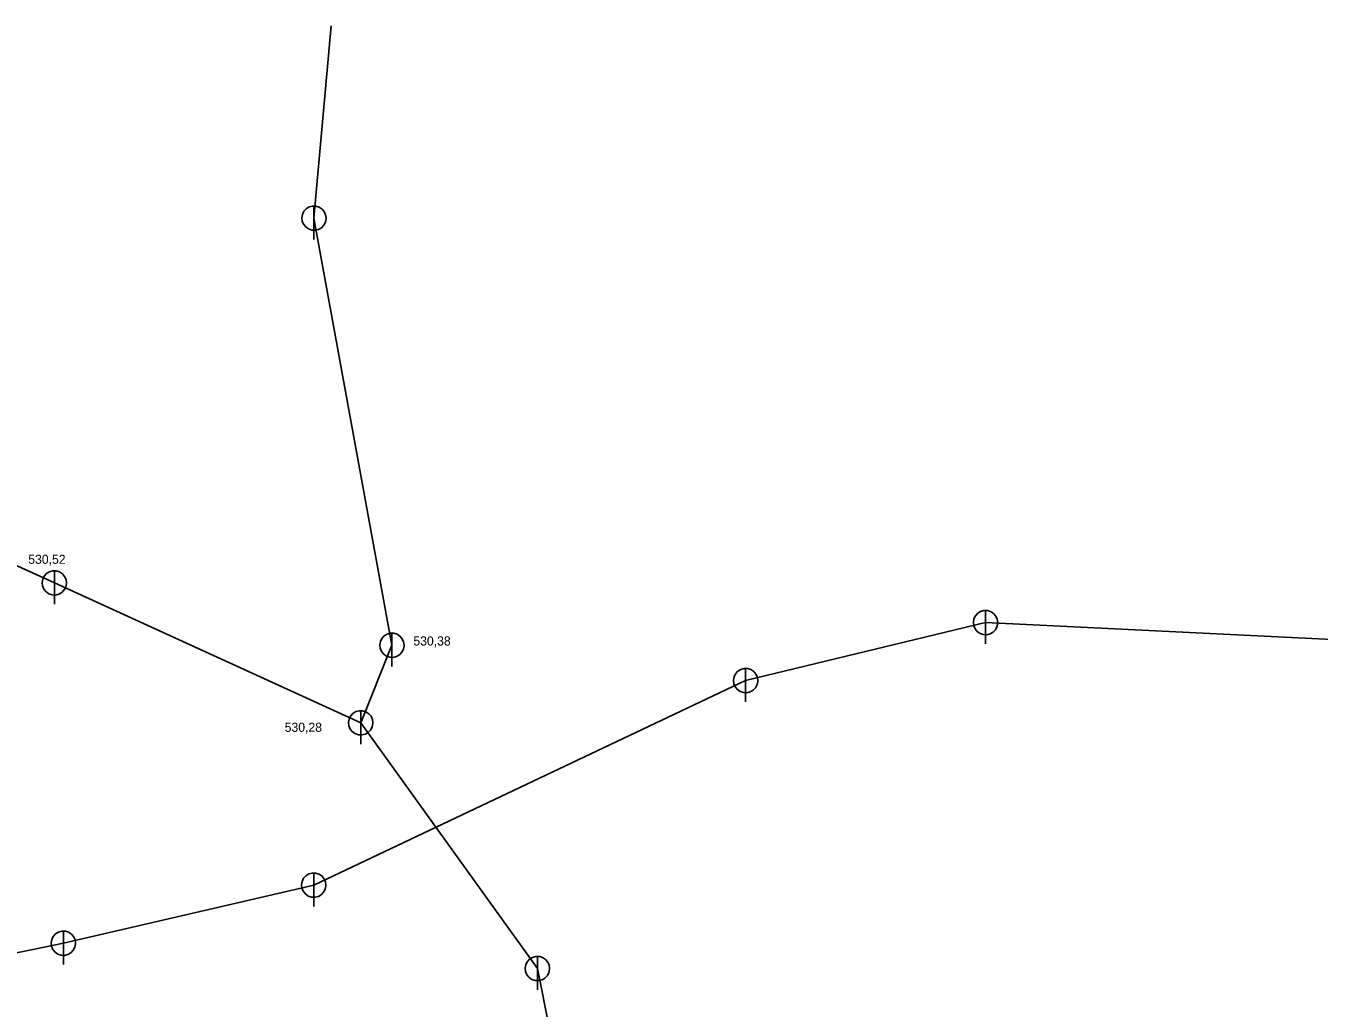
# Model space of a CAD drawing. Extents: x -476058 to -471893, y -1155786 to -1152000.
# Drawn here: x -473406.3 to -473300, y -1153831.2 to -1153750.3 of the extents above; entities that cross this region are included whole.
import ezdxf

# ---------------------------------------------------------------- set-up
doc = ezdxf.new("R2010")
doc.units = 0
for name, color, linetype in [('Vrstva 10', 7, 'Continuous'), ('Vrstva 3', 7, 'Continuous'), ('Vrstva 45', 7, 'Continuous'), ('Vrstva 46', 7, 'Continuous')]:
    doc.layers.add(name, color=color, linetype=linetype)

msp = doc.modelspace()

# ---------------------------------------------------------------- linework, layer by layer
at = {"layer": 'Vrstva 10'}
for p, q in [((-473382.66, -1153765.16), (-473382.66, -1153767.91)), ((-473404, -1153795.17), (-473404, -1153797.92)), ((-473327.45, -1153798.44), (-473327.45, -1153801.19)), ((-473376.25, -1153800.3), (-473376.25, -1153803.05)), ((-473347.17, -1153803.21), (-473347.17, -1153805.96)), ((-473378.82, -1153806.68), (-473378.82, -1153809.43)), ((-473382.68, -1153820.03), (-473382.68, -1153822.78)), ((-473403.26, -1153824.81), (-473403.26, -1153827.56)), ((-473364.29, -1153826.9), (-473364.29, -1153829.64))]:
    msp.add_line(p, q, dxfattribs=at)
for points in [[(-473381.66, -1153766.16), (-473381.7, -1153765.88), (-473381.82, -1153765.62), (-473382, -1153765.41), (-473382.23, -1153765.26), (-473382.51, -1153765.17), (-473382.79, -1153765.17), (-473383.06, -1153765.24), (-473383.3, -1153765.39), (-473383.49, -1153765.6), (-473383.61, -1153765.85), (-473383.66, -1153766.13), (-473383.63, -1153766.41), (-473383.52, -1153766.67), (-473383.34, -1153766.89), (-473383.11, -1153767.05), (-473382.84, -1153767.14), (-473382.56, -1153767.16), (-473382.29, -1153767.09), (-473382.04, -1153766.95), (-473381.85, -1153766.74), (-473381.72, -1153766.49), (-473381.66, -1153766.22), (-473381.66, -1153766.16)], [(-473403, -1153796.17), (-473403.04, -1153795.89), (-473403.16, -1153795.63), (-473403.34, -1153795.42), (-473403.58, -1153795.27), (-473403.85, -1153795.18), (-473404.13, -1153795.18), (-473404.4, -1153795.25), (-473404.64, -1153795.4), (-473404.83, -1153795.61), (-473404.96, -1153795.86), (-473405, -1153796.14), (-473404.97, -1153796.42), (-473404.86, -1153796.68), (-473404.68, -1153796.9), (-473404.45, -1153797.06), (-473404.19, -1153797.15), (-473403.9, -1153797.17), (-473403.63, -1153797.1), (-473403.39, -1153796.96), (-473403.19, -1153796.75), (-473403.06, -1153796.5), (-473403.01, -1153796.23), (-473403, -1153796.17)], [(-473326.45, -1153799.44), (-473326.49, -1153799.16), (-473326.61, -1153798.9), (-473326.79, -1153798.69), (-473327.03, -1153798.53), (-473327.29, -1153798.45), (-473327.58, -1153798.45), (-473327.85, -1153798.52), (-473328.09, -1153798.67), (-473328.28, -1153798.88), (-473328.4, -1153799.13), (-473328.45, -1153799.41), (-473328.42, -1153799.69), (-473328.31, -1153799.95), (-473328.13, -1153800.17), (-473327.9, -1153800.33), (-473327.63, -1153800.42), (-473327.35, -1153800.44), (-473327.08, -1153800.37), (-473326.83, -1153800.23), (-473326.64, -1153800.02), (-473326.51, -1153799.77), (-473326.45, -1153799.5), (-473326.45, -1153799.44)], [(-473375.25, -1153801.3), (-473375.29, -1153801.02), (-473375.41, -1153800.76), (-473375.59, -1153800.55), (-473375.83, -1153800.4), (-473376.1, -1153800.31), (-473376.38, -1153800.31), (-473376.65, -1153800.38), (-473376.89, -1153800.53), (-473377.08, -1153800.74), (-473377.2, -1153800.99), (-473377.25, -1153801.27), (-473377.22, -1153801.55), (-473377.11, -1153801.81), (-473376.93, -1153802.03), (-473376.7, -1153802.19), (-473376.43, -1153802.28), (-473376.15, -1153802.3), (-473375.88, -1153802.23), (-473375.63, -1153802.09), (-473375.44, -1153801.88), (-473375.31, -1153801.63), (-473375.25, -1153801.36), (-473375.25, -1153801.3)], [(-473346.17, -1153804.21), (-473346.21, -1153803.93), (-473346.33, -1153803.67), (-473346.51, -1153803.46), (-473346.75, -1153803.3), (-473347.02, -1153803.22), (-473347.3, -1153803.22), (-473347.57, -1153803.29), (-473347.81, -1153803.44), (-473348, -1153803.65), (-473348.12, -1153803.9), (-473348.17, -1153804.18), (-473348.14, -1153804.46), (-473348.03, -1153804.72), (-473347.85, -1153804.94), (-473347.62, -1153805.1), (-473347.35, -1153805.19), (-473347.07, -1153805.21), (-473346.8, -1153805.14), (-473346.55, -1153805), (-473346.36, -1153804.79), (-473346.23, -1153804.54), (-473346.17, -1153804.27), (-473346.17, -1153804.21)], [(-473377.82, -1153807.68), (-473377.86, -1153807.4), (-473377.97, -1153807.14), (-473378.16, -1153806.93), (-473378.39, -1153806.78), (-473378.66, -1153806.69), (-473378.94, -1153806.69), (-473379.22, -1153806.76), (-473379.46, -1153806.91), (-473379.65, -1153807.12), (-473379.77, -1153807.37), (-473379.82, -1153807.65), (-473379.79, -1153807.93), (-473379.68, -1153808.19), (-473379.5, -1153808.41), (-473379.27, -1153808.57), (-473379, -1153808.66), (-473378.72, -1153808.68), (-473378.44, -1153808.61), (-473378.2, -1153808.47), (-473378, -1153808.26), (-473377.87, -1153808.01), (-473377.82, -1153807.74), (-473377.82, -1153807.68)], [(-473381.68, -1153821.03), (-473381.72, -1153820.75), (-473381.84, -1153820.5), (-473382.02, -1153820.28), (-473382.25, -1153820.13), (-473382.52, -1153820.04), (-473382.81, -1153820.04), (-473383.08, -1153820.11), (-473383.32, -1153820.26), (-473383.51, -1153820.47), (-473383.63, -1153820.73), (-473383.68, -1153821), (-473383.65, -1153821.28), (-473383.54, -1153821.54), (-473383.36, -1153821.76), (-473383.13, -1153821.93), (-473382.86, -1153822.02), (-473382.58, -1153822.03), (-473382.3, -1153821.96), (-473382.06, -1153821.82), (-473381.87, -1153821.61), (-473381.74, -1153821.36), (-473381.68, -1153821.09), (-473381.68, -1153821.03)], [(-473402.26, -1153825.81), (-473402.3, -1153825.53), (-473402.42, -1153825.27), (-473402.6, -1153825.06), (-473402.84, -1153824.91), (-473403.1, -1153824.82), (-473403.39, -1153824.82), (-473403.66, -1153824.89), (-473403.9, -1153825.04), (-473404.09, -1153825.25), (-473404.21, -1153825.5), (-473404.26, -1153825.78), (-473404.23, -1153826.06), (-473404.12, -1153826.32), (-473403.94, -1153826.54), (-473403.71, -1153826.7), (-473403.44, -1153826.79), (-473403.16, -1153826.81), (-473402.89, -1153826.74), (-473402.64, -1153826.6), (-473402.45, -1153826.39), (-473402.32, -1153826.14), (-473402.26, -1153825.87), (-473402.26, -1153825.81)], [(-473363.29, -1153827.9), (-473363.33, -1153827.62), (-473363.44, -1153827.36), (-473363.63, -1153827.14), (-473363.86, -1153826.99), (-473364.13, -1153826.91), (-473364.41, -1153826.9), (-473364.69, -1153826.98), (-473364.93, -1153827.13), (-473365.12, -1153827.33), (-473365.24, -1153827.59), (-473365.29, -1153827.87), (-473365.26, -1153828.15), (-473365.15, -1153828.41), (-473364.97, -1153828.63), (-473364.74, -1153828.79), (-473364.47, -1153828.88), (-473364.19, -1153828.89), (-473363.91, -1153828.82), (-473363.67, -1153828.68), (-473363.47, -1153828.48), (-473363.34, -1153828.23), (-473363.29, -1153827.95), (-473363.29, -1153827.9)]]:
    msp.add_lwpolyline(points, dxfattribs=at)
at = {"layer": 'Vrstva 45'}
for points in [[(-473382.66, -1153766.16), (-473376.25, -1153801.3)], [(-473421.7, -1153788.12), (-473404, -1153796.17)], [(-473404, -1153796.17), (-473378.82, -1153807.68)], [(-473376.25, -1153801.3), (-473378.82, -1153807.68)], [(-473378.82, -1153807.68), (-473364.29, -1153827.9)], [(-473403.26, -1153825.81), (-473412.99, -1153827.8)]]:
    msp.add_lwpolyline(points, dxfattribs=at)
at = {"layer": 'Vrstva 46'}
for points in [[(-473381.26, -1153750.34), (-473382.66, -1153766.16)], [(-473327.45, -1153799.44), (-473347.17, -1153804.21)], [(-473289.45, -1153801.29), (-473327.45, -1153799.44)], [(-473347.17, -1153804.21), (-473382.68, -1153821.03)], [(-473382.68, -1153821.03), (-473403.26, -1153825.81)], [(-473364.29, -1153827.9), (-473362.3, -1153837.83)]]:
    msp.add_lwpolyline(points, dxfattribs=at)

# ---------------------------------------------------------------- texts
at = {"layer": 'Vrstva 3'}
for s, p in [('530,52', (-473406.15, -1153794.6)), ('530,38', (-473374.49, -1153801.32)), ('530,28', (-473385.07, -1153808.42))]:
    msp.add_text(s, height=0.75, dxfattribs=at).set_placement(p)

doc.saveas('drawing.dxf')
